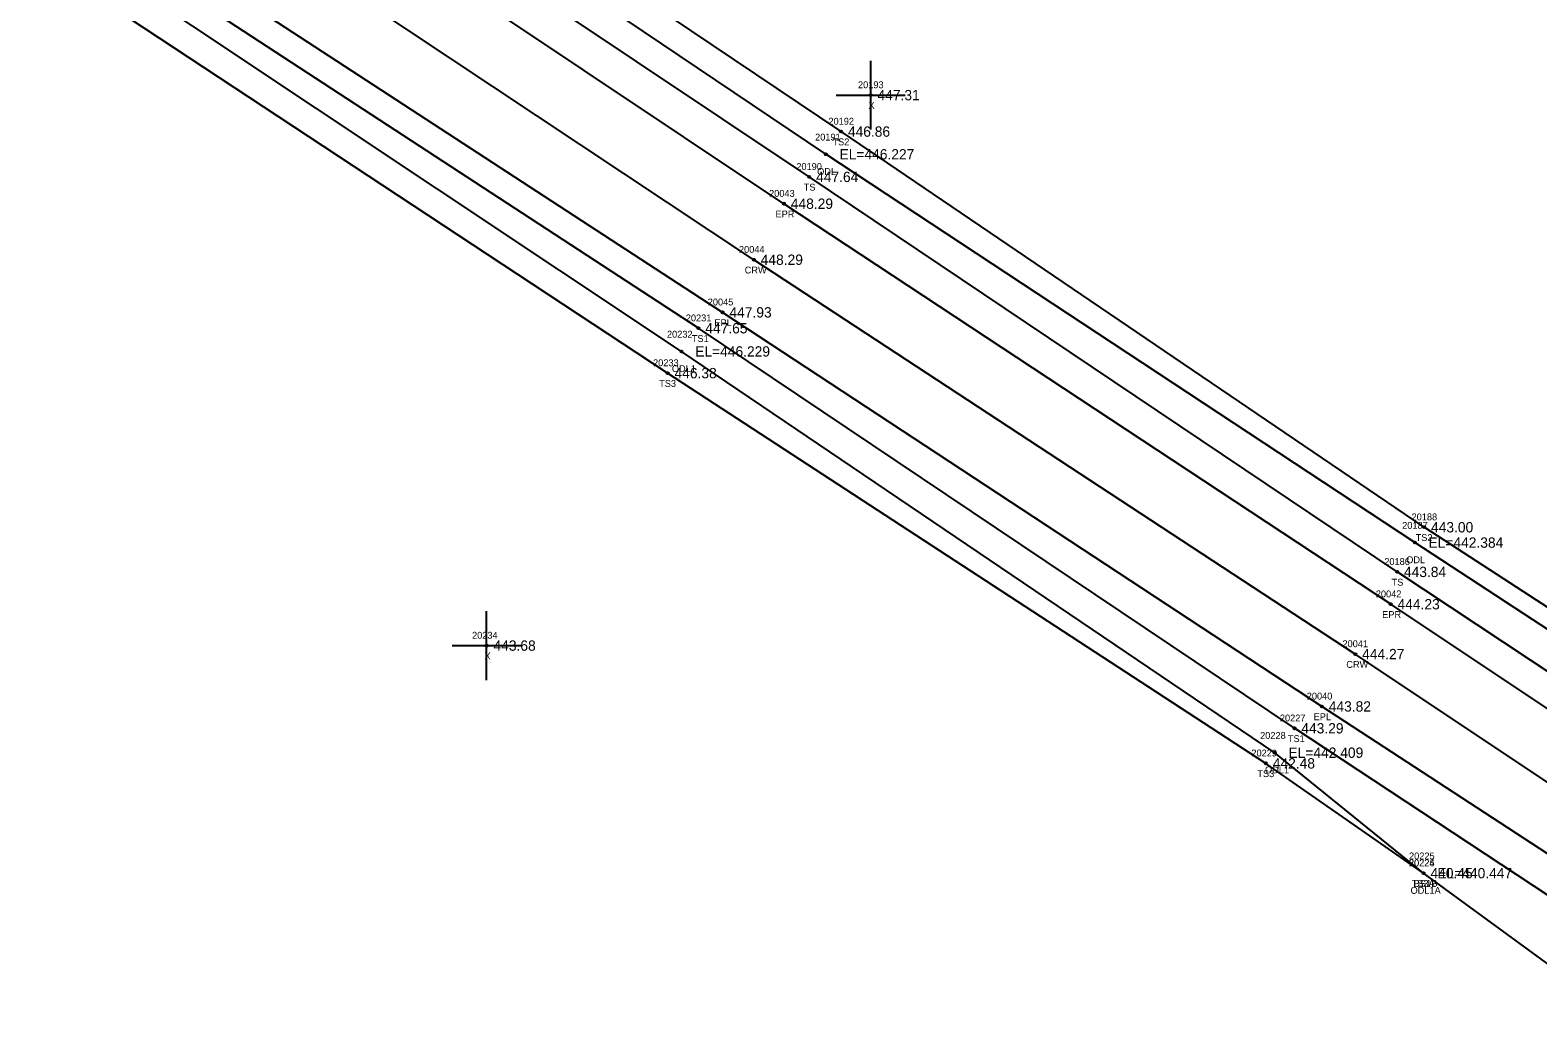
# Model space of a CAD drawing. Extents: x 1797709 to 1799052, y 896018 to 896955.
# Drawn here: x 1797995.4 to 1798214.6, y 896561.4 to 896704.4 of the extents above; entities that cross this region are included whole.
import ezdxf

# ---------------------------------------------------------------- set-up
doc = ezdxf.new("R2010")
doc.units = 0
for name, color, linetype in [('RD_DTM_BkLn1', 7, 'Continuous'), ('RD_DTM_BkLn2', 7, 'Continuous'), ('RD_DTM_BkLn_txCode', 7, 'Continuous'), ('RD_EX_H2O', 7, 'Continuous'), ('RD_EX_H2O_txCode', 7, 'Continuous'), ('RD_EX_Misc', 7, 'Continuous'), ('RD_EX_Misc_txCode', 7, 'Continuous'), ('RD_EX_Road', 7, 'Continuous'), ('RD_EX_Road_txCode', 7, 'Continuous'), ('RD_EX_TX_H2O_ELEV', 7, 'Continuous'), ('RD_EX_TX_Misc_ELEV', 7, 'Continuous'), ('RD_EX_TX_Road_ELEV', 7, 'Continuous'), ('RD_HC_Survey_ELEV', 7, 'Continuous'), ('RD_HC_Survey_txCode', 7, 'Continuous'), ('RD_SMD_Locator', 7, 'Continuous')]:
    doc.layers.add(name, color=color, linetype=linetype)

msp = doc.modelspace()

# ---------------------------------------------------------------- linework, layer by layer
at = {"layer": 'RD_DTM_BkLn1'}
msp.add_lwpolyline([(1798362.28, 896497.65), (1798275.53, 896555.51), (1798188.06, 896613.78), (1798100.6, 896671.09), (1798012.14, 896729.83), (1797925.7, 896787.19), (1797839.16, 896844.44), (1797754.21, 896899.34)], dxfattribs=at)
at = {"layer": 'RD_DTM_BkLn2'}
for points in [[(1798369.83, 896508.31), (1798367.91, 896513.92), (1798355.6, 896518.28), (1798283.49, 896566.57), (1798194.13, 896625.72), (1798108.66, 896683.13), (1798020.94, 896741.77), (1797934.88, 896798.69), (1797845.83, 896857.42), (1797757.7, 896918.3)], [(1798314.49, 896563.64), (1798288.01, 896573.8), (1798198.07, 896632.21), (1798113.28, 896689.71), (1798026.02, 896748.38), (1797939.51, 896805.48), (1797849.3, 896863.45), (1797757.7, 896918.3)], [(1798355.54, 896486.7), (1798350.74, 896485.38), (1798342.98, 896495.49), (1798267.09, 896545.1), (1798179.21, 896602.99), (1798092.54, 896661.13), (1798003.24, 896719.48), (1797918.21, 896775.43), (1797832.05, 896831.86), (1797744.82, 896887.66)], [(1798197.99, 896581.94), (1798175.06, 896597.9), (1798088.07, 896654.61), (1797998.87, 896713.42), (1797913.47, 896768.94), (1797829.42, 896827.1), (1797825.33, 896819.91), (1797827.32, 896807.68), (1797867.99, 896748.59)], [(1798360.17, 896479.84), (1798351.9, 896475.41), (1798259.06, 896537.39), (1798197.99, 896581.94)]]:
    msp.add_lwpolyline(points, dxfattribs=at)
at = {"layer": 'RD_EX_H2O'}
for points in [[(1798314.49, 896563.64), (1798286.18, 896571.49), (1798196.7, 896629.98), (1798111.06, 896686.41), (1798023.38, 896745.41), (1797937.01, 896802.03), (1797847.56, 896860.46), (1797757.7, 896918.3)], [(1798197.99, 896581.94), (1798176.34, 896599.45), (1798090.08, 896657.76), (1798001.35, 896716.83), (1797917.02, 896773.77), (1797830.54, 896829.07), (1797814.36, 896825.45)]]:
    msp.add_lwpolyline(points, dxfattribs=at)
at = {"layer": 'RD_EX_Misc'}
for p, q in [((1798117.59, 896690.01), (1798117.59, 896700.01)), ((1798112.59, 896695.01), (1798122.59, 896695.01)), ((1798061.75, 896610.01), (1798061.75, 896620.01)), ((1798056.75, 896615.01), (1798066.75, 896615.01))]:
    msp.add_line(p, q, dxfattribs=at)
at = {"layer": 'RD_EX_Road'}
for points in [[(1798362.28, 896497.65), (1798367.54, 896505.07), (1798280.71, 896562.69), (1798193.2, 896621.02), (1798104.98, 896679.23), (1798017.88, 896737.39), (1797930.72, 896795.63), (1797844.07, 896853.07), (1797758.11, 896906.97)], [(1798362.28, 896497.65), (1798357.85, 896490.18), (1798271.29, 896548.71), (1798183.2, 896606.17), (1798096.06, 896663.44), (1798006.57, 896721.75), (1797920.8, 896779.27), (1797834.41, 896836.87), (1797748.77, 896891.01)]]:
    msp.add_lwpolyline(points, dxfattribs=at)
at = {"layer": 'RD_SMD_Locator'}
for centre in [(1798117.59, 896695.01), (1798113.28, 896689.71), (1798111.06, 896686.41), (1798108.66, 896683.13), (1798104.98, 896679.23), (1798100.6, 896671.09), (1798096.06, 896663.44), (1798092.54, 896661.13), (1798090.08, 896657.76), (1798088.07, 896654.61), (1798198.07, 896632.21), (1798196.7, 896629.98), (1798194.13, 896625.72), (1798193.2, 896621.02), (1798061.75, 896615.01), (1798188.06, 896613.78), (1798183.2, 896606.17), (1798179.21, 896602.99), (1798175.06, 896597.9), (1798176.34, 896599.45), (1798197.99, 896581.94), (1798197.99, 896581.94), (1798197.99, 896581.94)]:
    msp.add_circle(centre, 0.15, dxfattribs=at)

# ---------------------------------------------------------------- texts
at = {"layer": 'RD_DTM_BkLn_txCode'}
for s, p in [('20192', (1798111.45, 896690.71)), ('TS2', (1798112.04, 896687.71)), ('20190', (1798106.78, 896684.13)), ('TS', (1798107.86, 896681.13)), ('20231', (1798090.71, 896662.13)), ('TS1', (1798091.58, 896659.13)), ('20233', (1798085.95, 896655.61)), ('TS3', (1798086.83, 896652.61)), ('20188', (1798196.24, 896633.21)), ('TS2', (1798196.83, 896630.21)), ('20186', (1798192.27, 896626.72)), ('TS', (1798193.33, 896623.72)), ('20227', (1798177.09, 896603.99)), ('TS1', (1798178.25, 896600.99)), ('20229', (1798172.95, 896598.9)), ('TS3', (1798173.82, 896595.9)), ('20226', (1798195.85, 896582.94)), ('20224', (1798195.87, 896582.94)), ('TS3A', (1798196.26, 896579.94)), ('BS1B', (1798196.57, 896579.94))]:
    msp.add_text(s, height=1, dxfattribs=at).set_placement(p)
at = {"layer": 'RD_EX_H2O_txCode'}
for s, p in [('20191', (1798109.51, 896688.41)), ('ODL', (1798109.81, 896683.41)), ('20232', (1798087.97, 896659.76)), ('ODL1', (1798088.68, 896654.76)), ('20187', (1798194.87, 896631.98)), ('ODL', (1798195.46, 896626.98)), ('20228', (1798174.22, 896601.45)), ('ODL1', (1798174.93, 896596.45)), ('20225', (1798195.87, 896583.94)), ('ODL1A', (1798196.09, 896578.94))]:
    msp.add_text(s, height=1, dxfattribs=at).set_placement(p)
at = {"layer": 'RD_EX_Misc_txCode'}
for s, p in [('20193', (1798115.75, 896696.01)), ('X', (1798117.27, 896693.01)), ('20234', (1798059.63, 896616.01)), ('X', (1798061.43, 896613.01))]:
    msp.add_text(s, height=1, dxfattribs=at).set_placement(p)
at = {"layer": 'RD_EX_Road_txCode'}
for s, p in [('20043', (1798102.82, 896680.23)), ('EPR', (1798103.75, 896677.23)), ('20045', (1798093.9, 896664.44)), ('EPL', (1798094.86, 896661.44)), ('20042', (1798191.04, 896622.02)), ('EPR', (1798191.97, 896619.02)), ('20040', (1798181, 896607.17)), ('EPL', (1798182, 896604.17))]:
    msp.add_text(s, height=1, dxfattribs=at).set_placement(p)
at = {"layer": 'RD_EX_TX_H2O_ELEV'}
for s, p in [('EL=446.227', (1798113.06, 896685.66)), ('EL=446.229', (1798092.08, 896657.01)), ('EL=442.384', (1798198.7, 896629.23)), ('EL=442.409', (1798178.34, 896598.7)), ('EL=440.447', (1798199.99, 896581.19))]:
    msp.add_text(s, height=1.5, dxfattribs=at).set_placement(p)
at = {"layer": 'RD_EX_TX_Misc_ELEV'}
for s, p in [('447.31', (1798118.59, 896694.26)), ('446.86', (1798114.28, 896688.96)), ('447.64', (1798109.66, 896682.38)), ('447.65', (1798093.54, 896660.38)), ('446.38', (1798089.07, 896653.86)), ('443.00', (1798199.07, 896631.46)), ('443.84', (1798195.13, 896624.97)), ('443.68', (1798062.75, 896614.26)), ('443.29', (1798180.21, 896602.24)), ('442.48', (1798176.06, 896597.15)), ('440.45', (1798198.99, 896581.19)), ('440.45', (1798198.99, 896581.19))]:
    msp.add_text(s, height=1.5, dxfattribs=at).set_placement(p)
at = {"layer": 'RD_EX_TX_Road_ELEV'}
for s, p in [('448.29', (1798105.98, 896678.48)), ('447.93', (1798097.06, 896662.69)), ('444.23', (1798194.2, 896620.27)), ('443.82', (1798184.2, 896605.42))]:
    msp.add_text(s, height=1.5, dxfattribs=at).set_placement(p)
at = {"layer": 'RD_HC_Survey_ELEV'}
for s, p in [('448.29', (1798101.6, 896670.34)), ('444.27', (1798189.06, 896613.03))]:
    msp.add_text(s, height=1.5, dxfattribs=at).set_placement(p)
at = {"layer": 'RD_HC_Survey_txCode'}
for s, p in [('20044', (1798098.44, 896672.09)), ('CRW', (1798099.28, 896669.09)), ('20041', (1798186.19, 896614.78)), ('CRW', (1798186.75, 896611.78))]:
    msp.add_text(s, height=1, dxfattribs=at).set_placement(p)

doc.saveas('drawing.dxf')
